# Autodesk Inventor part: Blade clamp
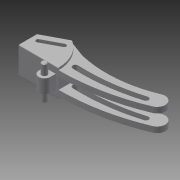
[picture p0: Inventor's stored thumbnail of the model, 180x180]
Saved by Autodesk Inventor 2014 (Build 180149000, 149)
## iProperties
Created: 2008-06
Part Number: Blade clamp
Document SubType Name: Modeling
Designer: tangg
Density: 7.85 g/cm^3
Mass: 7.32781 g
Surface Area: 54.7426 cm^2
Volume: 7.32781 cm^3
Stock Number: Blade clamp
Material: Steel
Appearance: Steel
Author: tangg
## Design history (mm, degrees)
sketch "Sketch14"
  geometry: L1 (7.937, 3.175)-(7.937, 0); L2 (1.587, 0)-(1.587, 3.175); L3 (7.937, 0)-(1.587, 0); L4 (7.937, 0)-(1.587, 0) reference; C1 r 1.587 at (4.762, 3.175); A1 r 3.175 centre (4.762, 3.175) between (7.937, 3.175) and (1.587, 3.175); 1 further point
  constraints: 8 end point, 2 centre point, 2 horizontal alignment, 2 point on circle, 1 coincident, 1 horizontal, 1 vertical, 1 other
  dimensions: "d57" = 6.35 distance of L1.end L2.start; "d58" = 3.175 radius of A1; "d59" = 3.175 diameter of C1
extrude "Extrusion18" join sketch "Sketch14" stored distance "d68" = 7.62; taper "d69" = 0 deg
sketch "Sketch30"
  geometry: L1 (0, 0)-(22.663, 0); L2 (22.663, 0)-(22.663, -10.474); L3 (22.663, -10.474)-(9.865, -17.21); L4 (9.865, -17.21)-(0.414, -13.728); L5 (0, 0)-(-3.829, 0); L6 (18.185, -6.295)-(8.665, -11.306); L7 (19.215, -8.324)-(9.724, -13.319); L8 (1.587, 0)-(7.937, 0) reference; L9 (0, -114.3)-(-43.989, -8.804); A1 r 1.137 centre (18.7, -7.309) between (19.215, -8.324) and (18.185, -6.295); A2 r 1.137 centre (9.194, -12.312) between (8.665, -11.306) and (9.724, -13.319); A3 r 114.3 centre (0, -114.3) between (0, 0) and (-43.989, -8.804); A4 r 66.779 centre (-14.826, -78.745) between (0.414, -13.728) and (-40.526, -17.11); A5 r 4.499 centre (-42.258, -12.957) between (-43.989, -8.804) and (-40.526, -17.11)
  constraints: 16 end point, 10 point on circle, 5 centre point, 2 point on line, 1 collinear, 1 parallel, 1 tangent, 1 vertical alignment
  dimensions: "d110" = 114.3 radius of A3
extrude "Extrusion28" join sketch "Sketch30" stored distance "d102" = 15.24; taper "d103" = 0 deg
sketch "Sketch36"
  geometry: L1 (19.244, -8.308)-(9.724, -13.319); L2 (18.185, -6.295)-(8.665, -11.306); A1 r 1.137 centre (18.715, -7.302) between (19.244, -8.308) and (18.185, -6.295); A2 r 1.137 centre (9.194, -12.313) between (8.665, -11.306) and (9.724, -13.319); 1 further point
  constraints: 4 end point, 4 point on circle, 2 centre point, 1 parallel
extrude "Extrusion29" cut sketch "Sketch36" stored distance "d104" = 15.24; taper "d105" = 0 deg
sketch "Sketch38"
  geometry: A1 r 106.726 centre (-7.616, -112.905) between (-1.587, -6.35) and (-39.688, -11.113); 2 further points
  constraints: 2 point on circle, 1 centre point
extrude_surface "ExtrusionSrf3" sketch "Sketch38" dims "d106" = 15.24, "d107" = 0
thicken "Thicken2" dims "d108" = 3
fillet "Fillet5" dims "d109" = 1.5
sketch "Sketch33"
  geometry: L1 (18.185, -6.295)-(8.665, -11.306) reference; L2 (9.724, -13.319)-(19.244, -8.308) reference; L3 (7.937, 0)-(22.663, 0) reference; L4 (22.663, 0)-(22.663, -10.474) reference; L5 (22.663, -10.474)-(9.865, -17.21) reference; L6 (9.865, -17.21)-(0.414, -13.728) reference; L7 (0, 0)-(1.587, 0) reference; L8 (1.587, 0)-(1.587, 3.175) reference; L9 (7.937, 3.175)-(7.937, 0) reference; L10 (0, 0)-(0, -13.632); C1 r 1.587 at (4.762, 3.175) reference; A1 r 1.137 centre (18.715, -7.302) between (19.244, -8.308) and (18.185, -6.295) reference; A2 r 1.137 centre (9.194, -12.313) between (8.665, -11.306) and (9.724, -13.319) reference; A3 r 66.779 centre (-14.826, -78.745) between (0.414, -13.728) and (-40.526, -17.11) reference; A4 r 4.499 centre (-42.258, -12.957) between (-43.989, -8.804) and (-40.526, -17.11) reference; A5 r 114.3 centre (0, -114.3) between (0, 0) and (-43.989, -8.804) reference; A6 r 3.175 centre (4.762, 3.175) between (7.937, 3.175) and (1.587, 3.175) reference; A7 r 1.5 centre (-38.254, -10.672) between (-38.684, -9.235) and (-37.823, -12.109) reference; A8 r 105.226 centre (-7.616, -112.905) between (-3.149, -7.774) and (-37.823, -12.109) reference; A9 r 1.5 centre (-3.086, -6.276) between (-3.149, -7.774) and (-3.022, -4.777) reference; A10 r 106.726 centre (-7.616, -112.905) between (-1.587, -6.35) and (-39.688, -11.113) reference; A11 r 108.226 centre (-7.616, -112.905) between (-3.022, -4.777) and (-38.684, -9.235) reference
  constraints: 2 end point, 1 point on circle
extrude "Extrusion25" cut sketch "Sketch33" stored distance "d93" = 6.35; taper "d94" = 0 deg
sketch "Sketch41"
  geometry: L1 (-0.414, -13.728)-(-9.865, -17.21) reference; L2 (-22.663, 0)-(0, 0) reference; A1 r 114.3 centre (0, -114.3) between (43.989, -8.804) and (0, 0) reference; A2 r 4.499 centre (42.258, -12.957) between (40.526, -17.11) and (43.989, -8.804) reference; A3 r 66.779 centre (14.826, -78.745) between (40.526, -17.11) and (-0.414, -13.728) reference; A4 r 19.944 centre (-19.944, 0) between (-9.865, -17.21) and (0, 0)
  constraints: 2 point on circle, 1 centre point, 1 point on line
extrude "Extrusion30" cut sketch "Sketch41" distance "d111" = 1.27; taper "d112" = 0 deg
mirror "Mirror2"
sketch "Sketch44"
  geometry: A1 r 105.226 centre (7.616, -112.905) between (37.823, -12.109) and (3.149, -7.774) reference; A2 r 1.5 centre (3.086, -6.276) between (3.022, -4.777) and (3.149, -7.774) reference; A3 r 1.5 centre (38.254, -10.672) between (37.823, -12.109) and (38.684, -9.235) reference; A4 r 108.226 centre (7.616, -112.905) between (38.684, -9.235) and (3.022, -4.777) reference; 1 further point
sketch "Sketch45"
  geometry: C1 r 1.524 at (4.763, 3.175); 1 further point
  constraints: 1 centre point
  dimensions: "d114" = 3.048 diameter of C1
extrude "Extrusion31" join sketch "Sketch45" stored distance "d115" = 19.05; taper "d116" = 0 deg
chamfer "Chamfer1" distance "d117" = 0.3175; stored, may be unused: second distance "d118" = 3.175, angle "d119" = 45 deg
fillet "Fillet6" dims "d120" = 0.635
sketch "Sketch47"
  geometry: L1 (-1.588, 7.366)-(-11.113, 7.366); L2 (-11.113, 7.366)-(-11.113, 6.604); L3 (-11.113, 6.604)-(-1.587, 6.604); L4 (-1.587, 6.604)-(-1.588, 7.366); 2 further points
  constraints: 8 end point, 1 horizontal alignment, 1 midpoint
  dimensions: "d127" = 0.762 distance of L3.end L1.start; "d128" = 9.525 distance of L2.end L3.end
extrude "Extrusion33" cut sketch "Sketch47" distance "d124" = 17.78; taper "d125" = 0 deg
body "Solid1"
body "Srf1"
workplane "Work Plane6"
node "Project Cut Edges2"
